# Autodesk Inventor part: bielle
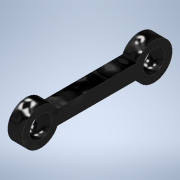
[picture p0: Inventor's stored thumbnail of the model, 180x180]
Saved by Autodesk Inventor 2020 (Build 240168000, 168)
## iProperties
Created: 2023-10
Part Number: bielle
Material: Générique
Document SubType Name: Modeling
Designer: bruno
Density: 1 g/cm^3
Appearance: Noir
Author: bruno
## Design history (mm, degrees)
sketch "Esquisse1" dims "d0" = 10
  geometry: L1 (2, -4.583)-(-2, -4.583); L2 (-2, -4.583)-(-2, -27.454); L3 (-2, -27.454)-(2, -27.454); L4 (2, -27.454)-(2, -4.583); C1 r 5 at (0, -31); C2 r 3 at (0, 0); C3 r 3 at (0, -31); 5 further points
  constraints: 8 end point, 3 centre point, 3 coincident, 2 parallel, 1 horizontal, 1 perpendicular, 3 other
  dimensions: "d1" = 4 distance between parallel lines of L2 L4; "d2" = 2 distance from line of L4 point (0, 0); "d3" = 10 diameter of C1; "d4" = 31 distance of C1.centre point (0, 0); "d5" = 6 diameter of C2; "d6" = 6 diameter of C3
extrude "Extrusion1" new body sketch "Esquisse1" distance "d7" = 4; taper "d8" = 0 deg
node "Solide1"
